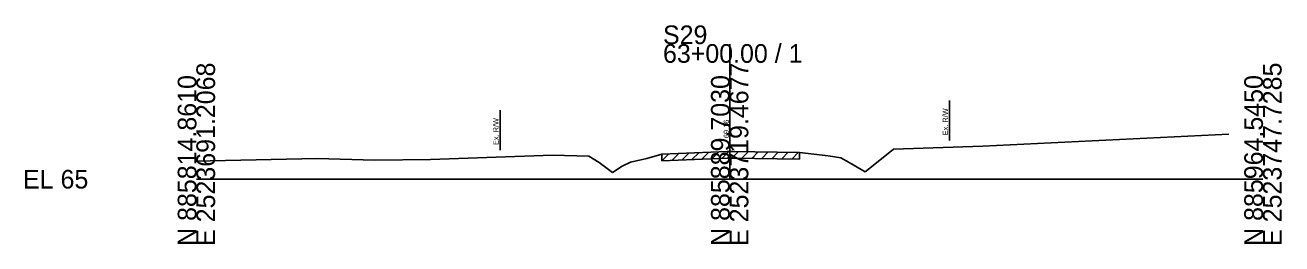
# Model space of a CAD drawing. Extents: x -26 to 163, y -10 to 4024.
# Drawn here: x -25.7 to 162.8, y 2490.3 to 2523.1 of the extents above; entities that cross this region are included whole.
import ezdxf

# ---------------------------------------------------------------- set-up
doc = ezdxf.new("R2010")
doc.units = 0
for name, color, linetype in [('RD_GPK_XS_Cell', 7, 'Continuous'), ('RD_XS_ExGround', 7, 'Continuous'), ('RD_XS_ExPaveRet', 7, 'Continuous'), ('RD_XS_ExRW', 7, 'Continuous'), ('RD_XS_TX_Elev_EX', 7, 'Continuous')]:
    doc.layers.add(name, color=color, linetype=linetype)

msp = doc.modelspace()

# ---------------------------------------------------------------- linework, layer by layer
at = {"layer": 'RD_GPK_XS_Cell'}
for p, q in [((80, 2500), (80, 2520.25)), ((0, 2500), (80, 2500)), ((80, 2500), (160, 2500))]:
    msp.add_line(p, q, dxfattribs=at)
at = {"layer": 'RD_XS_ExGround'}
for p, q in [((117.97, 2504.97), (154.89, 2506.75)), ((67.56, 2503.12), (69.81, 2503.74)), ((69.81, 2503.74), (79.6, 2504.15)), ((79.6, 2504.15), (80.03, 2504.16)), ((80.03, 2504.16), (80.41, 2504.16)), ((80.41, 2504.16), (90.47, 2504.01)), ((90.47, 2504.01), (94.8, 2503.48)), ((101.76, 2502.24), (104.56, 2504.5)), ((104.56, 2504.5), (117.97, 2504.97)), ((0, 2502.68), (2.06, 2502.74)), ((2.06, 2502.74), (18.11, 2503.1)), ((18.11, 2503.1), (26.78, 2502.87)), ((26.78, 2502.87), (35.13, 2502.95)), ((35.13, 2502.95), (53.41, 2503.62)), ((53.41, 2503.62), (58.89, 2503.46)), ((58.89, 2503.46), (60.43, 2502.51)), ((60.43, 2502.51), (62.42, 2501.01)), ((62.42, 2501.01), (63.88, 2501.94)), ((63.88, 2501.94), (65.13, 2502.57)), ((65.13, 2502.57), (67.56, 2503.12)), ((94.8, 2503.48), (96.7, 2503.18)), ((96.7, 2503.18), (97.91, 2502.5)), ((97.91, 2502.5), (100.32, 2501.11)), ((100.32, 2501.11), (101.76, 2502.24))]:
    msp.add_line(p, q, dxfattribs=at)
at = {"layer": 'RD_XS_ExPaveRet'}
for p, q in [((69.81, 2502.74), (70.85, 2503.79)), ((69.81, 2502.74), (69.81, 2503.74)), ((71.31, 2502.8), (72.35, 2503.85)), ((72.81, 2502.87), (73.85, 2503.91)), ((74.31, 2502.93), (75.35, 2503.97)), ((75.81, 2502.99), (76.85, 2504.03)), ((77.31, 2503.05), (78.35, 2504.1)), ((78.81, 2503.11), (79.85, 2504.16)), ((80.31, 2503.16), (81.3, 2504.15)), ((81.81, 2503.14), (82.8, 2504.12)), ((83.31, 2503.12), (84.3, 2504.1)), ((84.81, 2503.09), (85.8, 2504.08)), ((86.31, 2503.07), (87.3, 2504.05)), ((87.81, 2503.05), (88.8, 2504.03)), ((89.31, 2503.02), (90.3, 2504.01)), ((90.47, 2504.01), (90.47, 2503.01)), ((69.81, 2502.74), (79.6, 2503.15)), ((79.6, 2503.15), (80.03, 2503.16)), ((80.03, 2503.16), (80.41, 2503.16)), ((80.41, 2503.16), (90.47, 2503.01))]:
    msp.add_line(p, q, dxfattribs=at)
at = {"layer": 'RD_XS_ExRW'}
for p, q in [((113, 2511.8), (113, 2505.8)), ((45.58, 2510.33), (45.58, 2504.33))]:
    msp.add_line(p, q, dxfattribs=at)

# ---------------------------------------------------------------- texts
at = {"layer": 'RD_GPK_XS_Cell'}
for s, p in [('S29', (70, 2520.25)), ('63+00.00 / 1', (70, 2517.45)), ('EL 65', (-26, 2498.6))]:
    msp.add_text(s, height=2.8, dxfattribs=at).set_placement(p)
for s, p in [('E 2523691.2068', (2.8, 2490)), ('E 2523719.4677', (82.8, 2490)), ('E 2523747.7285', (162.8, 2490)), ('N 885814.8610', (0, 2490)), ('N 885889.7030', (80, 2490)), ('N 885964.5450', (160, 2490))]:
    msp.add_text(s, height=2.8, rotation=90, dxfattribs=at).set_placement(p)
at = {"layer": 'RD_XS_ExRW'}
for p in [(112.75, 2506.58), (45.33, 2505.12)]:
    msp.add_text('Ex. R/W ', height=0.8, rotation=90, dxfattribs=at).set_placement(p)
at = {"layer": 'RD_XS_TX_Elev_EX'}
msp.add_text('69.16', height=0.8, rotation=90, dxfattribs=at).set_placement((79.9, 2506.16))

doc.saveas('drawing.dxf')
